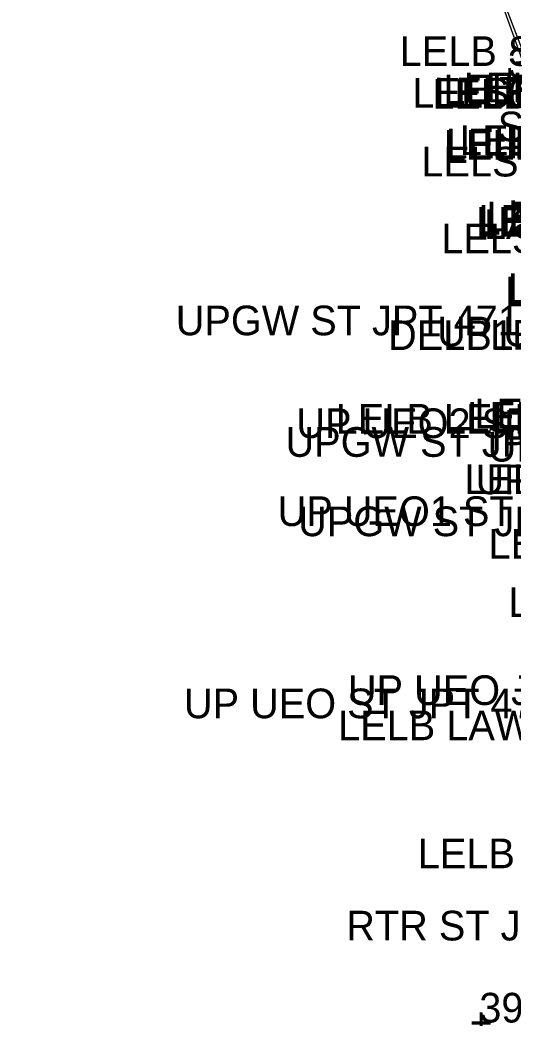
# Model space of a CAD drawing. Extents: x 1040177 to 1042343, y 1125540 to 1129143.
# Drawn here: x 1040335.5 to 1040501.6, y 1127826.3 to 1128162.7 of the extents above; entities that cross this region are included whole.
import ezdxf

# ---------------------------------------------------------------- set-up
doc = ezdxf.new("R2010")
doc.units = 0
for name, color, linetype in [('CDEFAULT', 7, 'Continuous'), ('COCOD', 7, 'Continuous'), ('COELE', 7, 'Continuous'), ('COPNT', 7, 'Continuous'), ('LABL', 7, 'Continuous'), ('LELS', 7, 'Continuous'), ('UEO', 7, 'Continuous')]:
    doc.layers.add(name, color=color, linetype=linetype)

msp = doc.modelspace()

# ---------------------------------------------------------------- linework, layer by layer
at = {"layer": 'LABL'}
msp.add_lwpolyline([(1040522.79, 1128098.94), (1040494.07, 1128178.95)], dxfattribs=at)
at = {"layer": 'LELS'}
for points in [[(1040499.02, 1128143.18), (1040499.81, 1128143.18)], [(1040499.81, 1128143.97), (1040499.81, 1128143.18)], [(1040499.81, 1128143.18), (1040500.59, 1128143.18)], [(1040499.81, 1128143.18), (1040499.81, 1128142.39)]]:
    msp.add_lwpolyline(points, dxfattribs=at)
at = {"layer": 'UEO'}
msp.add_lwpolyline([(1040632.97, 1128031.81), (1040554.71, 1128002.16), (1040556.16, 1128023.89), (1040539.16, 1128062.72), (1040481.62, 1128213.13), (1040410.07, 1128402.7), (1040335.48, 1128595.35)], dxfattribs=at)

# ---------------------------------------------------------------- texts
at = {"layer": 'CDEFAULT'}
for height, p in [(10, (1040496.54, 1128138.18)), (0.0781, (1040499.79, 1128143.14)), (10, (1040499.57, 1128114.99)), (10, (1040486.94, 1127819.82))]:
    msp.add_text('+', height=height, dxfattribs=at).set_placement(p)
at = {"layer": 'COCOD'}
for s, height, p in [('LELB ST', 10, (1040463.41, 1128147.24)), ('LELS', 10, (1040467.68, 1128133.18)), ('LELB4', 10, (1040474.38, 1128132.88)), ('LELB3', 10, (1040474.85, 1128133.34)), ('LELB2', 10, (1040478.08, 1128134.29)), ('LELB1', 10, (1040484.96, 1128134.94)), ('LELS', 0.0781, (1040499.61, 1128143.1)), ('STSEW', 10, (1040496.42, 1128121.85)), ('LELB4', 10, (1040478.26, 1128115.65)), ('LELB3', 10, (1040478.88, 1128116.06)), ('LELB2', 10, (1040483.67, 1128117.18)), ('LELB1', 10, (1040491.64, 1128116.98)), ('LELS', 10, (1040470.71, 1128109.99)), ('LELB1', 10, (1040499.87, 1128091.98)), ('LELB4', 10, (1040489.1, 1128089.73)), ('LELB3', 10, (1040489.94, 1128090.43)), ('LABL', 10, (1040491.77, 1128088.94)), ('LELB2', 10, (1040492.64, 1128091.46)), ('LELS', 10, (1040477.42, 1128084.11)), ('LELB4', 10, (1040498.87, 1128066.27)), ('LELB3', 10, (1040499.77, 1128067.3)), ('UPGW ST JPT 4719', 10, (1040387.96, 1128056.47)), ('DELB1 ST DELB2 ST', 10, (1040459.48, 1128051.49)), ('UP UEO2', 10, (1040476.02, 1128052.72)), ('LELS', 10, (1040493.83, 1128051.63)), ('LELB2 ST', 10, (1040488.56, 1128025.07)), ('UP UEO2 ST JPT 4718 2601', 10, (1040428.58, 1128021.81)), ('LELB LELB4 ST', 10, (1040441.85, 1128023.3)), ('LELB3 ST', 10, (1040486.14, 1128023.92)), ('LELS', 10, (1040498.61, 1128021.3)), ('UPGW ST JPT 4718', 10, (1040424.94, 1128015.5)), ('UP UEO2', 10, (1040493.02, 1128013.89)), ('LELB LABL', 10, (1040485.18, 1128003.01)), ('UPGW ST JPT 4715', 10, (1040488.94, 1128002.89)), ('UP UEO1 ST UEO2', 10, (1040422.28, 1127992.16)), ('UPGW ST JPT 4716', 10, (1040429.19, 1127988.75)), ('LELB LABL', 10, (1040493.32, 1127981.17)), ('LELB LABL', 10, (1040499.97, 1127961.48)), ('UP UEO JPT 2603', 10, (1040445.95, 1127931.84)), ('UP UEO ST JPT 4716', 10, (1040390.71, 1127927.38)), ('LELB LAWA LABL ST', 10, (1040442.67, 1127919.97)), ('LELB ST LELB1 ST', 10, (1040469.49, 1127876.81)), ('RTR ST JPT 1291', 10, (1040445.4, 1127852.48))]:
    msp.add_text(s, height=height, dxfattribs=at).set_placement(p)
at = {"layer": 'COELE'}
for s, height, p in [('393.228', 10, (1040499.81, 1128143.18)), ('393.228', 0.0781, (1040499.81, 1128143.18)), ('393.616', 10, (1040490.21, 1127824.82))]:
    msp.add_text(s, height=height, dxfattribs=at).set_placement(p)
at = {"layer": 'COPNT'}
for height, p in [(0.0781, (1040499.81, 1128143.1)), (10, (1040499.81, 1128133.18))]:
    msp.add_text('6116', height=height, dxfattribs=at).set_placement(p)

doc.saveas('drawing.dxf')
